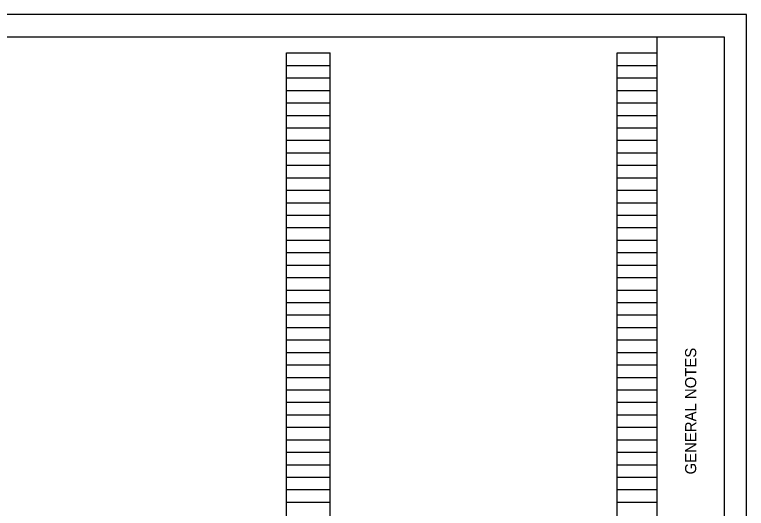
# Model space of a CAD drawing. Extents: x 0 to 34, y 0 to 22.
# Drawn here: x 17.58 to 34, y 10.92 to 22 of the extents above; entities that cross this region are included whole.
import ezdxf

# ---------------------------------------------------------------- set-up
doc = ezdxf.new("R2010")
doc.units = 0
for name, color, linetype in [('SH_Border', 7, 'Continuous'), ('SH_Cut_Line', 7, 'Continuous'), ('SH_Data', 7, 'Continuous')]:
    doc.layers.add(name, color=color, linetype=linetype)

msp = doc.modelspace()

# ---------------------------------------------------------------- linework, layer by layer
at = {"layer": 'SH_Border'}
msp.add_line((32, 0.5), (32, 21.5), dxfattribs=at)
msp.add_lwpolyline([(1.5, 21.5), (33.5, 21.5), (33.5, 0.5), (1.5, 0.5)], close=True, dxfattribs=at)
at = {"layer": 'SH_Cut_Line'}
msp.add_lwpolyline([(0, 0), (34, 0), (34, 22), (0, 22)], close=True, dxfattribs=at)
at = {"layer": 'SH_Data'}
for p, q in [((23.68, 0.98), (23.68, 21.14)), ((23.68, 21.14), (24.66, 21.14)), ((24.66, 0.98), (24.66, 21.14)), ((31.1, 0.98), (31.1, 21.14)), ((31.1, 21.14), (32, 21.14)), ((32, 0.98), (32, 21.14)), ((23.68, 20.86), (24.66, 20.86)), ((31.1, 20.86), (32, 20.86)), ((23.68, 20.58), (24.66, 20.58)), ((31.1, 20.58), (32, 20.58)), ((23.68, 20.3), (24.66, 20.3)), ((31.1, 20.3), (32, 20.3)), ((23.68, 20.02), (24.66, 20.02)), ((31.1, 20.02), (32, 20.02)), ((23.68, 19.74), (24.66, 19.74)), ((31.1, 19.74), (32, 19.74)), ((23.68, 19.46), (24.66, 19.46)), ((31.1, 19.46), (32, 19.46)), ((23.68, 19.18), (24.66, 19.18)), ((31.1, 19.18), (32, 19.18)), ((23.68, 18.9), (24.66, 18.9)), ((31.1, 18.9), (32, 18.9)), ((23.68, 18.62), (24.66, 18.62)), ((31.1, 18.62), (32, 18.62)), ((23.68, 18.34), (24.66, 18.34)), ((31.1, 18.34), (32, 18.34)), ((23.68, 18.06), (24.66, 18.06)), ((31.1, 18.06), (32, 18.06)), ((23.68, 17.78), (24.66, 17.78)), ((31.1, 17.78), (32, 17.78)), ((23.68, 17.5), (24.66, 17.5)), ((31.1, 17.5), (32, 17.5)), ((23.68, 17.22), (24.66, 17.22)), ((31.1, 17.22), (32, 17.22)), ((23.68, 16.94), (24.66, 16.94)), ((31.1, 16.94), (32, 16.94)), ((23.68, 16.66), (24.66, 16.66)), ((31.1, 16.66), (32, 16.66)), ((23.68, 16.38), (24.66, 16.38)), ((31.1, 16.38), (32, 16.38)), ((23.68, 16.1), (24.66, 16.1)), ((31.1, 16.1), (32, 16.1)), ((23.68, 15.82), (24.66, 15.82)), ((31.1, 15.82), (32, 15.82)), ((23.68, 15.54), (24.66, 15.54)), ((31.1, 15.54), (32, 15.54)), ((23.68, 15.26), (24.66, 15.26)), ((31.1, 15.26), (32, 15.26)), ((23.68, 14.98), (24.66, 14.98)), ((31.1, 14.98), (32, 14.98)), ((23.68, 14.7), (24.66, 14.7)), ((31.1, 14.7), (32, 14.7)), ((23.68, 14.42), (24.66, 14.42)), ((31.1, 14.42), (32, 14.42)), ((23.68, 14.14), (24.66, 14.14)), ((31.1, 14.14), (32, 14.14)), ((23.68, 13.86), (24.66, 13.86)), ((31.1, 13.86), (32, 13.86)), ((23.68, 13.58), (24.66, 13.58)), ((31.1, 13.58), (32, 13.58)), ((23.68, 13.3), (24.66, 13.3)), ((31.1, 13.3), (32, 13.3)), ((23.68, 13.02), (24.66, 13.02)), ((31.1, 13.02), (32, 13.02)), ((23.68, 12.74), (24.66, 12.74)), ((31.1, 12.74), (32, 12.74)), ((23.68, 12.46), (24.66, 12.46)), ((31.1, 12.46), (32, 12.46)), ((23.68, 12.18), (24.66, 12.18)), ((31.1, 12.18), (32, 12.18)), ((23.68, 11.9), (24.66, 11.9)), ((31.1, 11.9), (32, 11.9)), ((23.68, 11.62), (24.66, 11.62)), ((31.1, 11.62), (32, 11.62)), ((23.68, 11.34), (24.66, 11.34)), ((31.1, 11.34), (32, 11.34)), ((23.68, 11.06), (24.66, 11.06)), ((31.1, 11.06), (32, 11.06))]:
    msp.add_line(p, q, dxfattribs=at)

# ---------------------------------------------------------------- texts
msp.add_text('GENERAL NOTES', height=0.25, rotation=90, dxfattribs=at).set_placement((32.875, 11.682))

doc.saveas('drawing.dxf')
